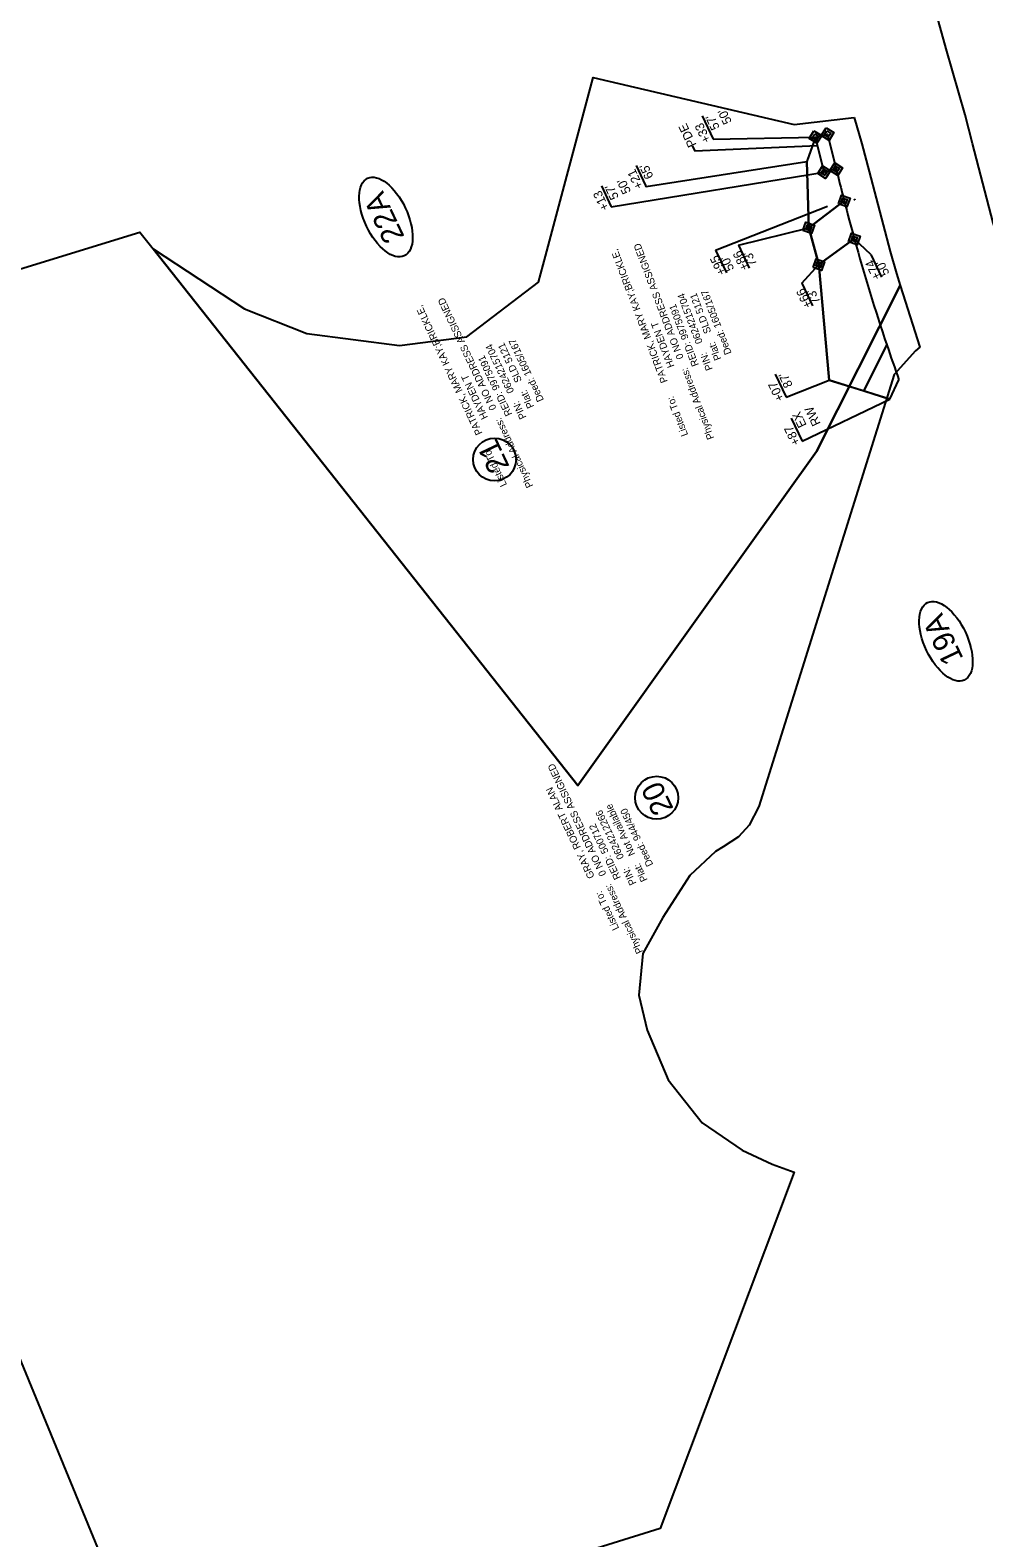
# Model space of a CAD drawing. Extents: x 1019969 to 1024963, y 638146 to 643978.
# Drawn here: x 1022170 to 1022703, y 641093 to 641936 of the extents above; entities that cross this region are included whole.
import ezdxf

# ---------------------------------------------------------------- set-up
doc = ezdxf.new("R2010")
doc.units = 0
for name, color, linetype in [('Old_Level_30', 7, 'Continuous'), ('Pattern 2', 7, 'Continuous'), ('Pattern 5', 7, 'Continuous'), ('Pattern 6', 7, 'Continuous'), ('Prop Easement Construction', 7, 'Continuous'), ('Prop Easement Construction Station Offsets', 7, 'Continuous'), ('Prop Easement Permanent Drainage', 7, 'Continuous'), ('Prop Easement Permanent Drainage Station Offsets', 7, 'Continuous'), ('Prop Parcel Number CELL', 7, 'Continuous'), ('Prop Parcel Owner Text', 7, 'Continuous'), ('Prop ROW Marker CELL', 7, 'Continuous'), ('Prop ROW Permanent Easement CELL', 7, 'Continuous'), ('Prop ROW RW Lines', 7, 'Continuous'), ('Scratch_Level_4', 7, 'Continuous')]:
    doc.layers.add(name, color=color, linetype=linetype)

msp = doc.modelspace()

# ---------------------------------------------------------------- linework, layer by layer
at = {"layer": 'Old_Level_30'}
msp.add_lwpolyline([(1022630.61, 641887.19), (1022634.81, 641872.56), (1022639, 641857.06), (1022650.81, 641812.31), (1022654.31, 641799.94), (1022656.38, 641793.19), (1022609.5, 641700.31), (1022553.82, 641622.45), (1022476, 641513.62), (1022238.3, 641813.78), (1022289.43, 641780.17), (1022324.39, 641766.47), (1022376.26, 641759.64), (1022413.92, 641764.52), (1022453.99, 641795.1), (1022457.9, 641809.73), (1022484.57, 641909.67), (1022597.11, 641883.3)], close=True, dxfattribs=at)
for points in [[(1022136.69, 641794.19), (1022231, 641823), (1022238.3, 641813.78), (1022476, 641513.62), (1022553.82, 641622.45), (1022609.5, 641700.31), (1022656.38, 641793.19), (1022657.88, 641788.5), (1022667.37, 641758.82), (1022664.92, 641756.67), (1022653.03, 641743.47), (1022577.33, 641501.71), (1022571.91, 641491.39), (1022565.83, 641484.85), (1022557.25, 641479.3), (1022553, 641476.55), (1022538.6, 641463.27), (1022523.57, 641439.79), (1022512.39, 641419.59), (1022510.14, 641396.35), (1022514.77, 641376.6), (1022526.45, 641348.93), (1022545.5, 641324.88), (1022567.96, 641309.51), (1022584.71, 641301.81), (1022597.04, 641297.18), (1022522.14, 641097.95), (1022372.73, 641051.29)], [(1022243.52, 640999.4), (1022204.78, 641093.44), (1022132.69, 641268.47)]]:
    msp.add_lwpolyline(points, dxfattribs=at)
at = {"layer": 'Pattern 2'}
for p, q in [((1022625.03, 641840.51), (1022605.17, 641825.5)), ((1022605.17, 641825.5), (1022610.84, 641804.9)), ((1022610.84, 641804.9), (1022630.69, 641819.27))]:
    msp.add_line(p, q, dxfattribs=at)
msp.add_lwpolyline([(1022620.56, 641858.31), (1022613.77, 641856.62), (1022608.93, 641876.29), (1022615.73, 641877.94)], close=True, dxfattribs=at)
msp.add_arc((1023713.95, 642119.35), 1124.06, 194.36356, 195.4838, dxfattribs=at)
at = {"layer": 'Pattern 6'}
for p, q in [((1022608.93, 641876.29), (1022604.45, 641863.69)), ((1022612.44, 641862), (1022608.93, 641876.29)), ((1022604.45, 641863.69), (1022604.05, 641862.57)), ((1022604.05, 641862.57), (1022605.17, 641825.5)), ((1022613.77, 641856.62), (1022612.44, 641862)), ((1022620.56, 641858.31), (1022613.77, 641856.62)), ((1022605.17, 641825.5), (1022625.03, 641840.51)), ((1022630.69, 641819.27), (1022610.84, 641804.9)), ((1022610.84, 641804.9), (1022616.53, 641740.24)), ((1022648.9, 641759.96), (1022636.1, 641734.25)), ((1022636.1, 641734.25), (1022648.9, 641759.96)), ((1022616.53, 641740.24), (1022636.1, 641734.25)), ((1022650.58, 641729.69), (1022655.65, 641740.53)), ((1022636.1, 641734.25), (1022650.58, 641729.69)), ((1022636.1, 641734.25), (1022636.1, 641734.25))]:
    msp.add_line(p, q, dxfattribs=at)
for centre, radius, start, end in [((1027003.05, 642947.53), 4515.82, 193.95746, 194.13293), ((1023713.95, 642119.35), 1124.06, 194.13293, 194.36356), ((1023713.95, 642119.35), 1124.06, 195.4838, 198.64645), ((1023713.95, 642119.35), 1124.06, 198.64645, 199.6953)]:
    msp.add_arc(centre, radius, start, end, dxfattribs=at)
at = {"layer": 'Prop Easement Construction'}
for p, q in [((1022608.93, 641876.29), (1022604.05, 641862.57)), ((1022605.17, 641825.5), (1022604.05, 641862.57)), ((1022616.53, 641740.24), (1022610.84, 641804.9)), ((1022650.58, 641729.69), (1022616.53, 641740.24))]:
    msp.add_line(p, q, dxfattribs=at)
at = {"layer": 'Prop Easement Construction Station Offsets'}
for p, q in [((1022508.55, 641860.45), (1022513.87, 641849.22)), ((1022586.42, 641743.66), (1022592.6, 641730.76)), ((1022595.34, 641719.02), (1022601.52, 641706.12))]:
    msp.add_line(p, q, dxfattribs=at)
for points in [[(1022513.87, 641849.22), (1022514.17, 641848.58), (1022604.05, 641862.57)], [(1022592.6, 641730.76), (1022616.53, 641740.24)], [(1022601.52, 641706.12), (1022650.58, 641729.69)]]:
    msp.add_lwpolyline(points, dxfattribs=at)
at = {"layer": 'Prop Easement Permanent Drainage'}
for p, q in [((1022608.93, 641876.29), (1022615.73, 641877.94)), ((1022613.77, 641856.62), (1022608.93, 641876.29)), ((1022620.56, 641858.31), (1022613.77, 641856.62)), ((1022605.17, 641825.5), (1022625.03, 641840.51)), ((1022610.84, 641804.9), (1022605.17, 641825.5)), ((1022610.84, 641804.9), (1022630.69, 641819.27))]:
    msp.add_line(p, q, dxfattribs=at)
at = {"layer": 'Prop Easement Permanent Drainage Station Offsets'}
for p, q in [((1022545.48, 641888.07), (1022551.66, 641875.03)), ((1022489.16, 641848.91), (1022494.65, 641837.31)), ((1022553.09, 641813.05), (1022559.08, 641800.39)), ((1022565.79, 641815.86), (1022571.93, 641802.88)), ((1022639.92, 641810.61), (1022645.95, 641797.87)), ((1022601.28, 641794.63), (1022607.3, 641781.92))]:
    msp.add_line(p, q, dxfattribs=at)
for points in [[(1022540.03, 641871.37), (1022541.36, 641868.57), (1022610.07, 641871.64)], [(1022551.66, 641875.03), (1022608.93, 641876.29)], [(1022494.65, 641837.31), (1022613.77, 641856.62)], [(1022553.09, 641813.05), (1022615.63, 641837.61)], [(1022565.79, 641815.86), (1022605.17, 641825.5)], [(1022639.92, 641810.61), (1022630.69, 641819.27)], [(1022601.28, 641794.63), (1022610.84, 641804.9)]]:
    msp.add_lwpolyline(points, dxfattribs=at)
at = {"layer": 'Prop Parcel Number CELL'}
for p, q in [((1022368.63, 641831.52), (1022368.63, 641831.52)), ((1022429.4, 641695.89), (1022429.4, 641695.89)), ((1022681.96, 641594.23), (1022681.96, 641594.23)), ((1022520.1, 641506.71), (1022520.1, 641506.71))]:
    msp.add_line(p, q, dxfattribs=at)
for centre in [(1022429.4, 641695.89), (1022520.1, 641506.71)]:
    msp.add_circle(centre, 12, dxfattribs=at)
for centre in [(1022368.63, 641831.52), (1022681.96, 641594.23)]:
    msp.add_ellipse(centre, major_axis=(-10.27, 21.69), ratio=0.5, dxfattribs=at)
at = {"layer": 'Prop ROW Marker CELL'}
for p, q in [((1022615.73, 641877.94), (1022615.73, 641877.94)), ((1022608.93, 641876.29), (1022608.93, 641876.29)), ((1022613.77, 641856.62), (1022613.77, 641856.62)), ((1022620.56, 641858.31), (1022620.56, 641858.31)), ((1022625.03, 641840.51), (1022625.03, 641840.51)), ((1022630.86, 641841.25), (1022630.86, 641841.25)), ((1022605.17, 641825.5), (1022605.17, 641825.5)), ((1022630.69, 641819.27), (1022630.69, 641819.27)), ((1022610.84, 641804.9), (1022610.84, 641804.9))]:
    msp.add_line(p, q, dxfattribs=at)
at = {"layer": 'Prop ROW Permanent Easement CELL'}
for points in [[(1022608.11, 641879.79), (1022612.43, 641877.1), (1022609.74, 641872.78), (1022605.42, 641875.47)], [(1022608.52, 641878.04), (1022610.68, 641876.69), (1022609.33, 641874.53), (1022607.17, 641875.88)], [(1022614.91, 641881.45), (1022619.23, 641878.76), (1022616.54, 641874.44), (1022612.22, 641877.13)], [(1022615.32, 641879.7), (1022617.48, 641878.35), (1022616.13, 641876.19), (1022613.97, 641877.54)], [(1022619.75, 641861.81), (1022624.07, 641859.12), (1022621.38, 641854.8), (1022617.05, 641857.49)], [(1022612.95, 641860.13), (1022617.27, 641857.43), (1022614.58, 641853.11), (1022610.26, 641855.8)], [(1022613.36, 641858.37), (1022615.52, 641857.03), (1022614.17, 641854.87), (1022612.01, 641856.21)], [(1022620.15, 641860.06), (1022622.31, 641858.71), (1022620.97, 641856.55), (1022618.81, 641857.9)], [(1022621.78, 641838.96), (1022623.49, 641843.76), (1022628.28, 641842.05), (1022626.57, 641837.25)], [(1022623.4, 641839.74), (1022624.26, 641842.13), (1022626.66, 641841.28), (1022625.8, 641838.88)], [(1022630.89, 641841.18), (1022630.8, 641841.22), (1022630.83, 641841.31), (1022630.93, 641841.28)], [(1022630.88, 641841.22), (1022630.83, 641841.23), (1022630.85, 641841.28), (1022630.89, 641841.26)], [(1022601.92, 641823.96), (1022603.63, 641828.75), (1022608.43, 641827.04), (1022606.71, 641822.25)], [(1022603.55, 641824.73), (1022604.4, 641827.13), (1022606.8, 641826.27), (1022605.94, 641823.87)], [(1022627.44, 641817.73), (1022629.15, 641822.52), (1022633.94, 641820.81), (1022632.23, 641816.02)], [(1022629.06, 641818.5), (1022629.92, 641820.9), (1022632.32, 641820.04), (1022631.46, 641817.64)], [(1022607.58, 641803.36), (1022609.3, 641808.16), (1022614.09, 641806.44), (1022612.38, 641801.65)], [(1022609.21, 641804.13), (1022610.07, 641806.53), (1022612.46, 641805.67), (1022611.61, 641803.28)]]:
    msp.add_lwpolyline(points, close=True, dxfattribs=at)
at = {"layer": 'Prop ROW RW Lines'}
msp.add_arc((1022167.9, 640774.19), 948.09, 40.00236, 40.00236, dxfattribs=at)
at = {"layer": 'Scratch_Level_4'}
msp.add_lwpolyline([(1023583.12, 641136.19), (1023429.39, 641289.91), (1023171, 641548.25), (1022965.69, 641750.69), (1022939.88, 641784.81), (1022904.19, 641833.5), (1022797.63, 642006.56), (1022717.5, 641847.75), (1022709.31, 641825.55), (1022708.37, 641828.25), (1022696.87, 641872.69), (1022692.62, 641888.75), (1022682, 641925.56), (1022675.88, 641947.75)], dxfattribs=at)

# ---------------------------------------------------------------- texts
at = {"layer": 'Old_Level_30'}
for s, p in [('0 NO ADDRESS ASSIGNED', (1022430.57, 641724.56)), ('PATRICK, MARY KAY;BRICKLE, ', (1022422.76, 641710.7)), ('0624215704', (1022440.47, 641734.03)), ('SLD 5121', (1022444.79, 641740.09)), ('1605/167', (1022450.26, 641743.74)), ('9975091', (1022432.48, 641735.72)), ('HAYDEN T', (1022425.8, 641719.46)), ('Plat:', (1022451.64, 641725.63)), ('Deed:', (1022457.11, 641729.28)), ('REID:', (1022439.33, 641721.26)), ('PIN:', (1022447.32, 641719.57)), ('Physical Address:', (1022451.12, 641681.18)), ('Listed To:', (1022436.45, 641681.78))]:
    msp.add_text(s, height=4, rotation=115.34303, dxfattribs=at).set_placement(p)
at = {"layer": 'Pattern 5'}
for s, rotation, p in [('PATRICK, MARY KAY;BRICKLE, ', 110.80114, (1022526.39, 641739.62)), ('0 NO ADDRESS ASSIGNED', 110.80114, (1022535.28, 641752.82)), ('0624215704', 110.80114, (1022545.9, 641761.48)), ('SLD 5121', 110.80114, (1022550.68, 641767.18)), ('1605/167', 110.80114, (1022556.42, 641770.38)), ('9975091', 110.80114, (1022538.06, 641763.79)), ('HAYDEN T', 110.80114, (1022530.11, 641748.12)), ('Deed:', 110.80114, (1022562.1, 641755.42)), ('REID:', 110.80114, (1022543.74, 641748.84)), ('Plat:', 110.80114, (1022556.36, 641752.22)), ('PIN:', 110.80114, (1022551.58, 641746.52)), ('Physical Address:', 110.80114, (1022552.32, 641707.95)), ('Listed To:', 110.80114, (1022537.75, 641709.71)), ('0 NO ADDRESS ASSIGNED', 115.34303, (1022492.04, 641463.96)), ('GRAY, ROBERT ALAN', 115.34303, (1022485.5, 641462.57)), ('0624212266', 115.34303, (1022501.98, 641473.34)), ('Not Available', 115.34303, (1022508.27, 641475.25)), ('944/450', 115.34303, (1022511.42, 641483.78)), ('500712', 115.34303, (1022493.31, 641476.46)), ('Deed:', 115.34303, (1022518.27, 641469.32)), ('REID:', 115.34303, (1022500.16, 641462)), ('PIN:', 115.34303, (1022508.83, 641458.88)), ('Plat:', 115.34303, (1022515.12, 641460.79)), ('Physical Address:', 115.34303, (1022512.58, 641420.58)), ('Listed To:', 115.34303, (1022499.2, 641433.65))]:
    msp.add_text(s, height=4, rotation=rotation, dxfattribs=at).set_placement(p)
at = {"layer": 'Prop Easement Construction Station Offsets'}
for s, rotation, p in [('+21', 115.34303, (1022512.79, 641848.59)), ("65'", 115.34303, (1022518.46, 641854.14)), ("87'", 115.60299, (1022596.35, 641737.4)), ('+07', 115.60299, (1022591.66, 641729.83)), ('EX', 115.60299, (1022604.13, 641715.14)), ('RW', 115.60299, (1022612, 641716.07)), ('+87', 115.60299, (1022600.58, 641705.2))]:
    msp.add_text(s, height=5, rotation=rotation, dxfattribs=at).set_placement(p)
at = {"layer": 'Prop Easement Permanent Drainage Station Offsets'}
for s, p in [("57'", (1022555.47, 641881.59)), ("50'", (1022562.25, 641884.8)), ('PDE', (1022542.5, 641872)), ('+33', (1022550.55, 641874.45)), ('+13', (1022493.63, 641836.55)), ("57'", (1022499.06, 641842.61)), ("50'", (1022505.83, 641845.82)), ('+86', (1022571.85, 641803.01)), ("73'", (1022576.41, 641805.17)), ('+95', (1022559.06, 641800.38)), ("50'", (1022563.62, 641802.54)), ('+74', (1022645.93, 641797.86)), ("50'", (1022650.49, 641800.02)), ('+66', (1022607.28, 641781.91)), ("73'", (1022611.84, 641784.07))]:
    msp.add_text(s, height=5, rotation=115.34303, dxfattribs=at).set_placement(p)
at = {"layer": 'Prop Parcel Owner Text'}
for s, p in [('22A', (1022379.23, 641820.51)), ('21', (1022438, 641691.93)), ('19A', (1022691.95, 641584.54)), ('20', (1022529.74, 641500.55))]:
    msp.add_text(s, height=12.15, rotation=115.34303, dxfattribs=at).set_placement(p)

doc.saveas('drawing.dxf')
